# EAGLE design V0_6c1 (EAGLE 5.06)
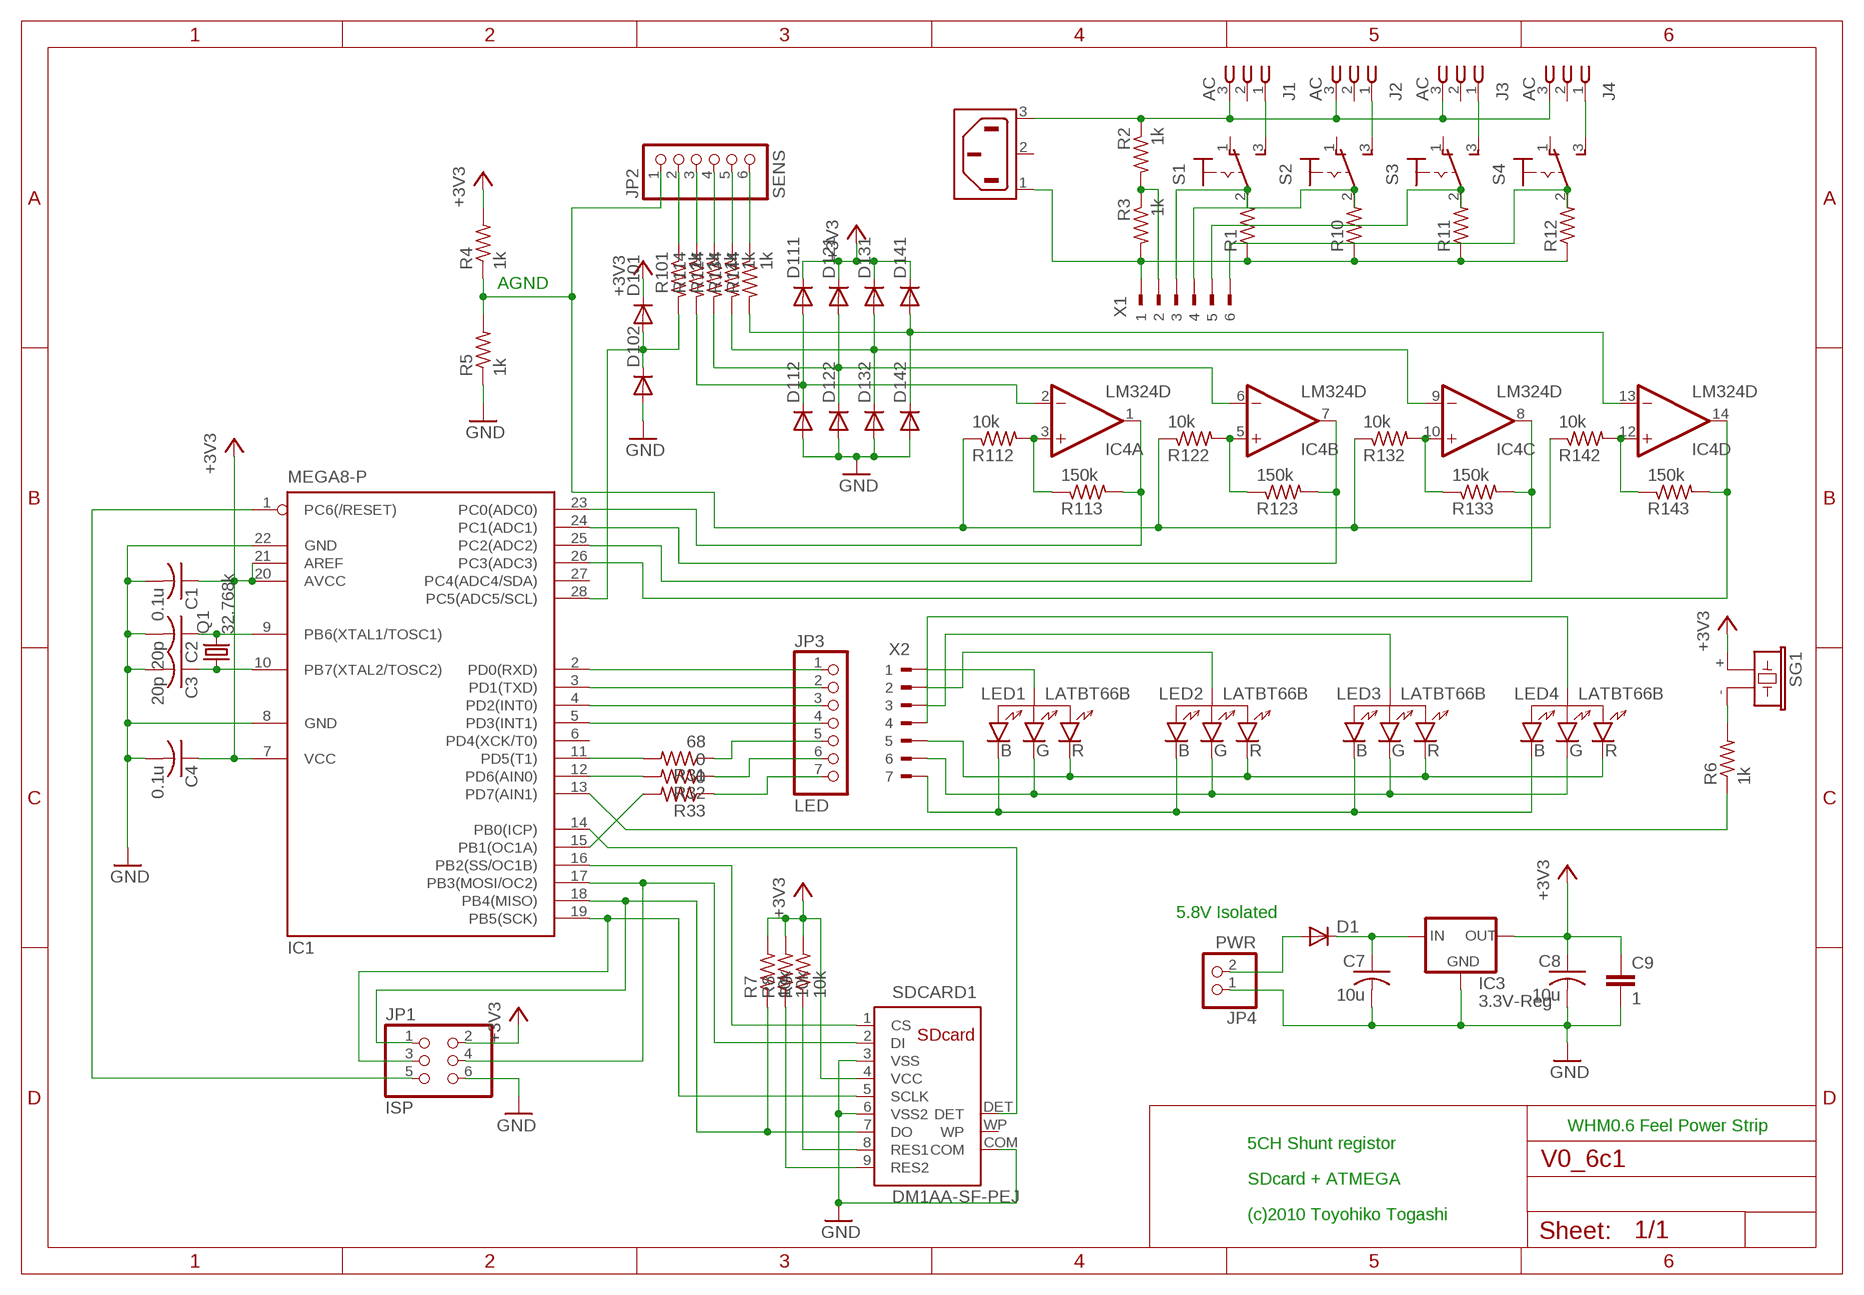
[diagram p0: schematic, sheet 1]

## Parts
C1  0.1u  C-US025-025X050  [C025-025X050]
C2  20p  C-US025-025X050  [C025-025X050]
C3  20p  C-US025-025X050  [C025-025X050]
C4  0.1u  C-US025-025X050  [C025-025X050]
C7  10u  C-US025-040X050  [C025-040X050]
C8  10u  C-US025-040X050  [C025-040X050]
C9  1  C7.5/4  [C7.5B4]
D1  BAS15  [DO34-7]
D101  BAS15  [DO34-7]
D102  BAS15  [DO34-7]
D111  BAS15  [DO34-7]
D112  BAS15  [DO34-7]
D121  BAS15  [DO34-7]
D122  BAS15  [DO34-7]
D131  BAS15  [DO34-7]
D132  BAS15  [DO34-7]
D141  BAS15  [DO34-7]
D142  BAS15  [DO34-7]
IC1  MEGA8-P  [DIL28-3]
IC3  3.3V-Reg  XC63FPM  [SOT23]
IC4  LM324D  [SO14]
J1  AC  213598-2  [213598-2]
J2  AC  213598-2  [213598-2]
J3  AC  213598-2  [213598-2]
J4  AC  213598-2  [213598-2]
JP1  ISP  PINHD-2X3  [2X03]
JP2  SENS  PINHD-1X6  [1X06]
JP3  LED  PINHD-1X7  [1X07]
JP4  PWR  PINHD-1X2  [1X02]
LED1  LATBT66B  [P-LCC-4]
LED2  LATBT66B  [P-LCC-4]
LED3  LATBT66B  [P-LCC-4]
LED4  LATBT66B  [P-LCC-4]
Q1  32.768k  CRYSTALTC26H  [TC26H]
R1  R-US_R6332  [R6332]
R2  1k  R-US_0204/5  [0204/5]
R3  1k  R-US_0204/5  [0204/5]
R4  1k  R-US_0204/5  [0204/5]
R5  1k  R-US_0204/5  [0204/5]
R6  1k  R-US_0204/5  [0204/5]
R7  10k  R-US_0204/5  [0204/5]
R8  10k  R-US_0204/5  [0204/5]
R9  10k  R-US_0204/5  [0204/5]
R10  R-US_R6332  [R6332]
R11  R-US_R6332  [R6332]
R12  R-US_R6332  [R6332]
R31  68  R-US_0204/5  [0204/5]
R32  0  R-US_0204/5  [0204/5]
R33  0  R-US_0204/5  [0204/5]
R101  1k  R-US_0204/5  [0204/5]
R112  10k  R-US_0204/5  [0204/5]
R113  150k  R-US_0204/5  [0204/5]
R114  1k  R-US_0204/5  [0204/5]
R122  10k  R-US_0204/5  [0204/5]
R123  150k  R-US_0204/5  [0204/5]
R124  1k  R-US_0204/5  [0204/5]
R132  10k  R-US_0204/5  [0204/5]
R133  150k  R-US_0204/5  [0204/5]
R134  1k  R-US_0204/5  [0204/5]
R142  10k  R-US_0204/5  [0204/5]
R143  150k  R-US_0204/5  [0204/5]
R144  1k  R-US_0204/5  [0204/5]
S1  320-916  [320-916]
S2  320-916  [320-916]
S3  320-916  [320-916]
S4  320-916  [320-916]
SDCARD1  DM1AA-SF-PEJ  [DM1AA]
SG1  F/CM12P  [F/CM12P]
X1  90-6  [90-6]
X2  90-7  [90-7]
X3  6ESRM-P  [6ESRM-P]

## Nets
+3V3: C1.1 C4.1 C8.1 C9.1 D101.C D111.C D121.C D131.C D141.C IC1.7(VCC) IC1.20(AVCC) IC1.21(AREF) IC3.2(OUT) JP1.2 R4.2 R7.2 R8.2 R9.2 SDCARD1.4(VCC) SG1.+
GND: C1.2 C2.2 C3.2 C4.2 C7.2 C8.2 C9.2 D102.A D112.A D122.A D132.A D142.A IC1.8(GND) IC1.22(GND) IC3.1(GND) JP1.6 JP4.1 R5.1 SDCARD1.3(VSS) SDCARD1.6(VSS2) SDCARD1.COM
N$2: D101.A D102.C IC1.28(PC5(ADC5/SCL)) R101.2
N$3: LED1.P$1 LED2.P$1 LED3.P$1 LED4.P$1 X2.5
N$4: D121.A D122.C IC4.6(B:-IN) R124.2
N$5: IC1.24(PC1(ADC1)) IC4.7(B:OUT) R123.2
N$6: D1.A JP4.2
N$7: C2.1 IC1.9(PB6(XTAL1/TOSC1)) Q1.2
N$8: LED1.P$4 LED2.P$4 LED3.P$4 LED4.P$4 X2.6
N$9: IC1.1(PC6(/RESET)) JP1.5
N$10: IC1.11(PD5(T1)) R31.2
N$11: C3.1 IC1.10(PB7(XTAL2/TOSC2)) Q1.1
N$12: JP2.2 R101.1
N$13: JP2.3 R114.1
N$14: IC1.3(PD1(TXD)) JP3.2
N$15: JP2.4 R124.1
N$16: IC1.4(PD2(INT0)) JP3.3
N$17: IC1.19(PB5(SCK)) JP1.3 SDCARD1.5(SCLK)
N$18: IC1.5(PD3(INT1)) JP3.4
N$19: IC4.3(A:+IN) R112.2 R113.1
N$20: IC4.5(B:+IN) R122.2 R123.1
N$21: IC1.13(PD7(AIN1)) R6.1
N$22: JP2.5 R134.1
N$23: IC1.23(PC0(ADC0)) IC4.1(A:OUT) R113.2
N$24: JP2.6 R144.1
N$25: IC1.2(PD0(RXD)) JP3.1
N$26: R6.2 SG1.-
N$27: JP3.5 R31.1
N$28: JP3.6 R32.1
N$29: IC4.10(C:+IN) R132.2 R133.1
N$30: JP3.7 R33.1
N$31: D111.A D112.C IC4.2(A:-IN) R114.2
N$32: IC1.17(PB3(MOSI/OC2)) JP1.4 SDCARD1.2(DI)
N$33: IC1.18(PB4(MISO)) JP1.1 R7.1 SDCARD1.7(DO)
N$34: JP2.1 R4.1 R5.2 R112.1 R122.1 R132.1 R142.1
N$35: IC1.15(PB1(OC1A)) R33.2
N$36: LED1.P$3 LED2.P$3 LED3.P$3 LED4.P$3 X2.7
N$37: LED1.P$2 X2.1
N$38: IC4.12(D:+IN) R142.2 R143.1
N$39: IC1.16(PB2(SS/OC1B)) SDCARD1.1(CS)
N$40: D131.A D132.C IC4.9(C:-IN) R134.2
N$41: R8.1 SDCARD1.9(RES2)
N$42: R9.1 SDCARD1.8(RES1)
N$43: IC1.14(PB0(ICP)) SDCARD1.DET
N$44: LED2.P$2 X2.2
N$45: LED3.P$2 X2.3
N$46: LED4.P$2 X2.4
N$47: IC1.12(PD6(AIN0)) R32.2
N$48: D141.A D142.C IC4.13(D:-IN) R144.2
N$49: R1.2 S1.2(P) X1.3
N$50: R2.2 R3.1 X1.2
N$51: J1.1 S1.3(S)
N$52: IC1.25(PC2(ADC2)) IC4.8(C:OUT) R133.2
N$53: IC1.26(PC3(ADC3)) IC4.14(D:OUT) R143.2
N$54: J1.3 J2.3 J3.3 J4.3 R2.1 X3.3(AC2)
N$55: R1.1 R3.2 R10.1 R11.1 R12.1 X1.1 X3.1(AC1)
N$56: C7.1 D1.C IC3.3(IN)
N$57: R10.2 S2.2(P) X1.4
N$58: R11.2 S3.2(P) X1.5
N$59: R12.2 S4.2(P) X1.6
N$60: J2.1 S2.3(S)
N$61: J3.1 S3.3(S)
N$62: J4.1 S4.3(S)
Unconnected: IC1.6(PD4(XCK/T0)) IC1.27(PC4(ADC4/SDA)) J1.2 J2.2 J3.2 J4.2 S1.1(O) S2.1(O) S3.1(O) S4.1(O) SDCARD1.WP X3.2(SH)

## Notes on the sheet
- AGND
- 5.8V Isolated
- WHM0.6 Feel Power Strip
- 5CH Shunt registor
- SDcard + ATMEGA
- (c)2010 Toyohiko Togashi

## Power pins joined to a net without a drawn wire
V+: IC4.4(P:V+)
V-: IC4.11(P:V-)

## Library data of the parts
C1-C4 C7 C8 = rcl:C-US: CAPACITOR, American symbol
C9 = capacitor-wima:C: CAPACITOR
D1 D101 D102 D111 D112 D121 D122 D131 D132 D141 D142 = diode:BAS15: DIODE
IC1 = atmel:MEGA8-P: MICROCONTROLLER 8 Kbytes FLASH, 1 kbytes SRAM, 512 bytes EEPROM, USART, 4-channel 10 bit ADC, 2-channel 8 bit ADC Pin compatible with Atmega48, ATMega88, ATMega168 Source: avr.lbr
IC3 = v-reg:XC63FP: Positiv Voltage Regulators www.torex.co.jp/english/product/pro02/pdf/0201_xc62fp.pdf
IC4 = linear:LM324: OP AMP
J1-J4 = con-amp:213598-2: AC Jack Source: ENG_CD_213598_M.pdf
JP1 = pinhead:PINHD-2X3: PIN HEADER
JP2 = pinhead:PINHD-1X6: PIN HEADER
JP3 = pinhead:PINHD-1X7: PIN HEADER
JP4 = pinhead:PINHD-1X2: PIN HEADER
LED1-LED4 = TOG:LATBT66B: RGB LED SMD
Q1 = crystal:CRYSTAL: CRYSTAL
R1-R12 R31-R33 R101 R112-R114 R122-R124 R132-R134 R142-R144 = rcl:R-US_: RESISTOR, American symbol
S1-S4 = switch:320-916: TOGGLE SWITCH distributor RS Components
SDCARD1 = TOG:DM1AA-SF-PEJ: SDcard connector HIROSE
SG1 = buzzer:F/CM12P: BUZZER
X1 = con-weidmueller-sl35:90-6: WEIDMUELLER CLAMP CONNECTOR
X2 = con-weidmueller-sl35:90-7: WEIDMUELLER CLAMP CONNECTOR
X3 = con-tycoelectronics:6ESRM-P: AC Connector 120/250 VAC Source: http://catalog.tycoelectronics.com .. ENG_DS_1654001_1099_SR_0406.pdf

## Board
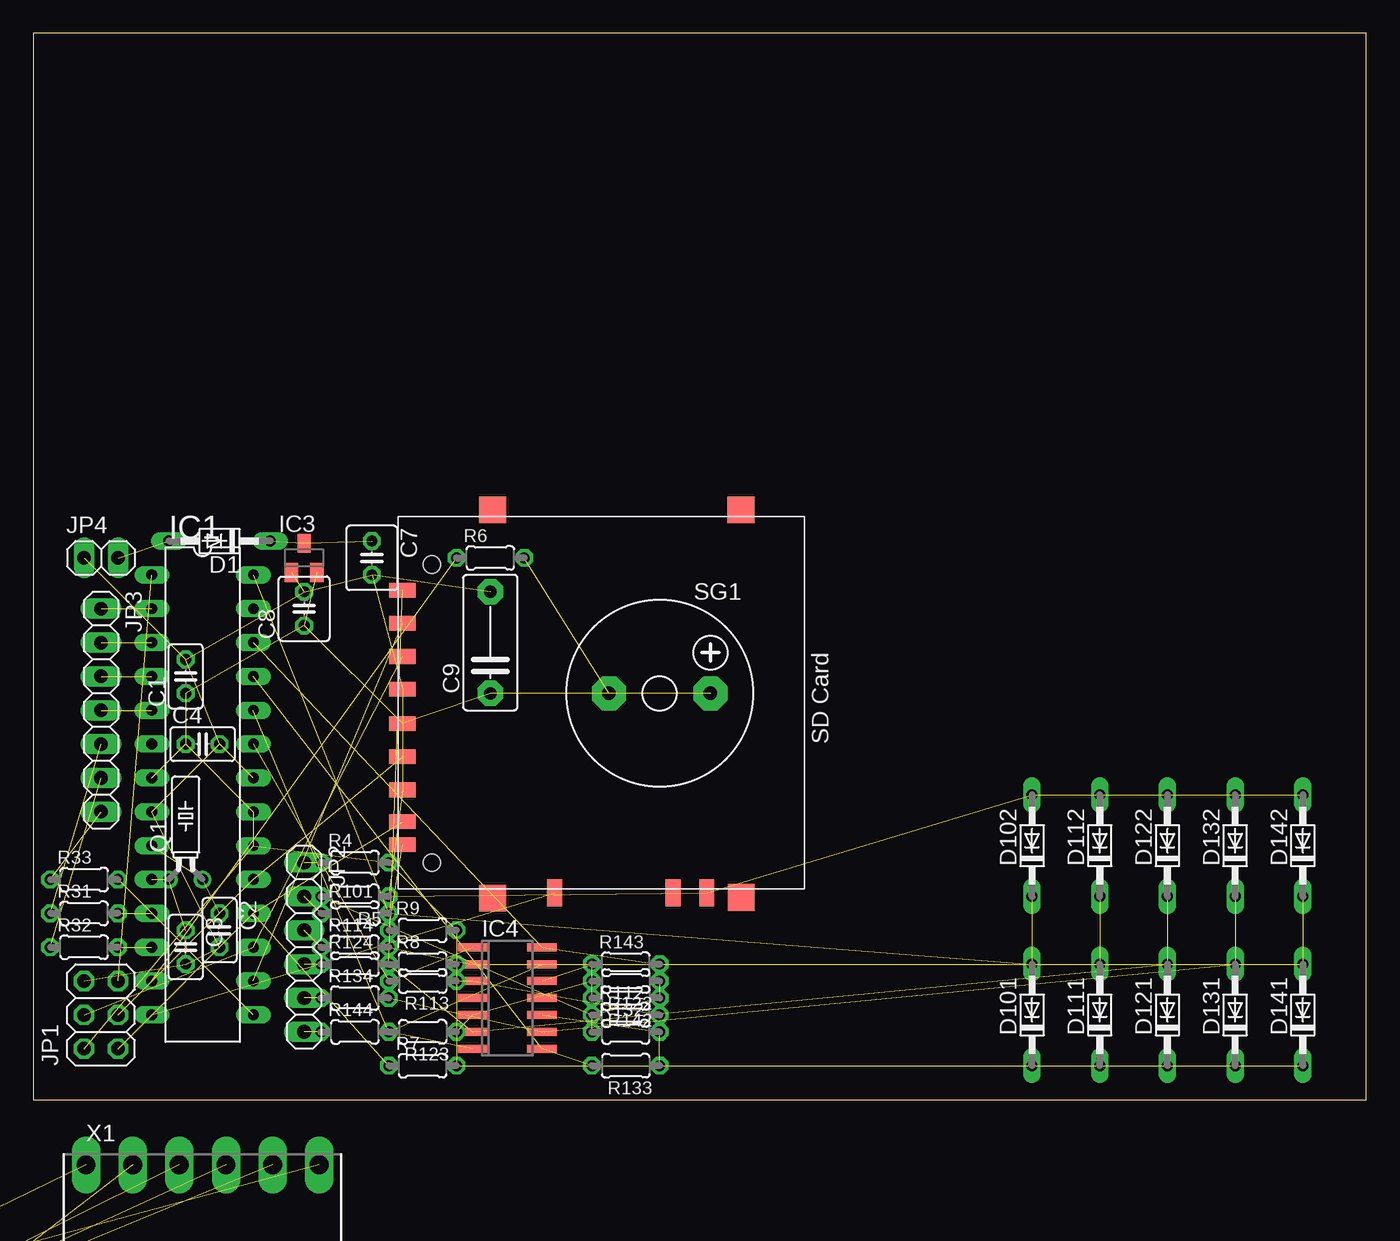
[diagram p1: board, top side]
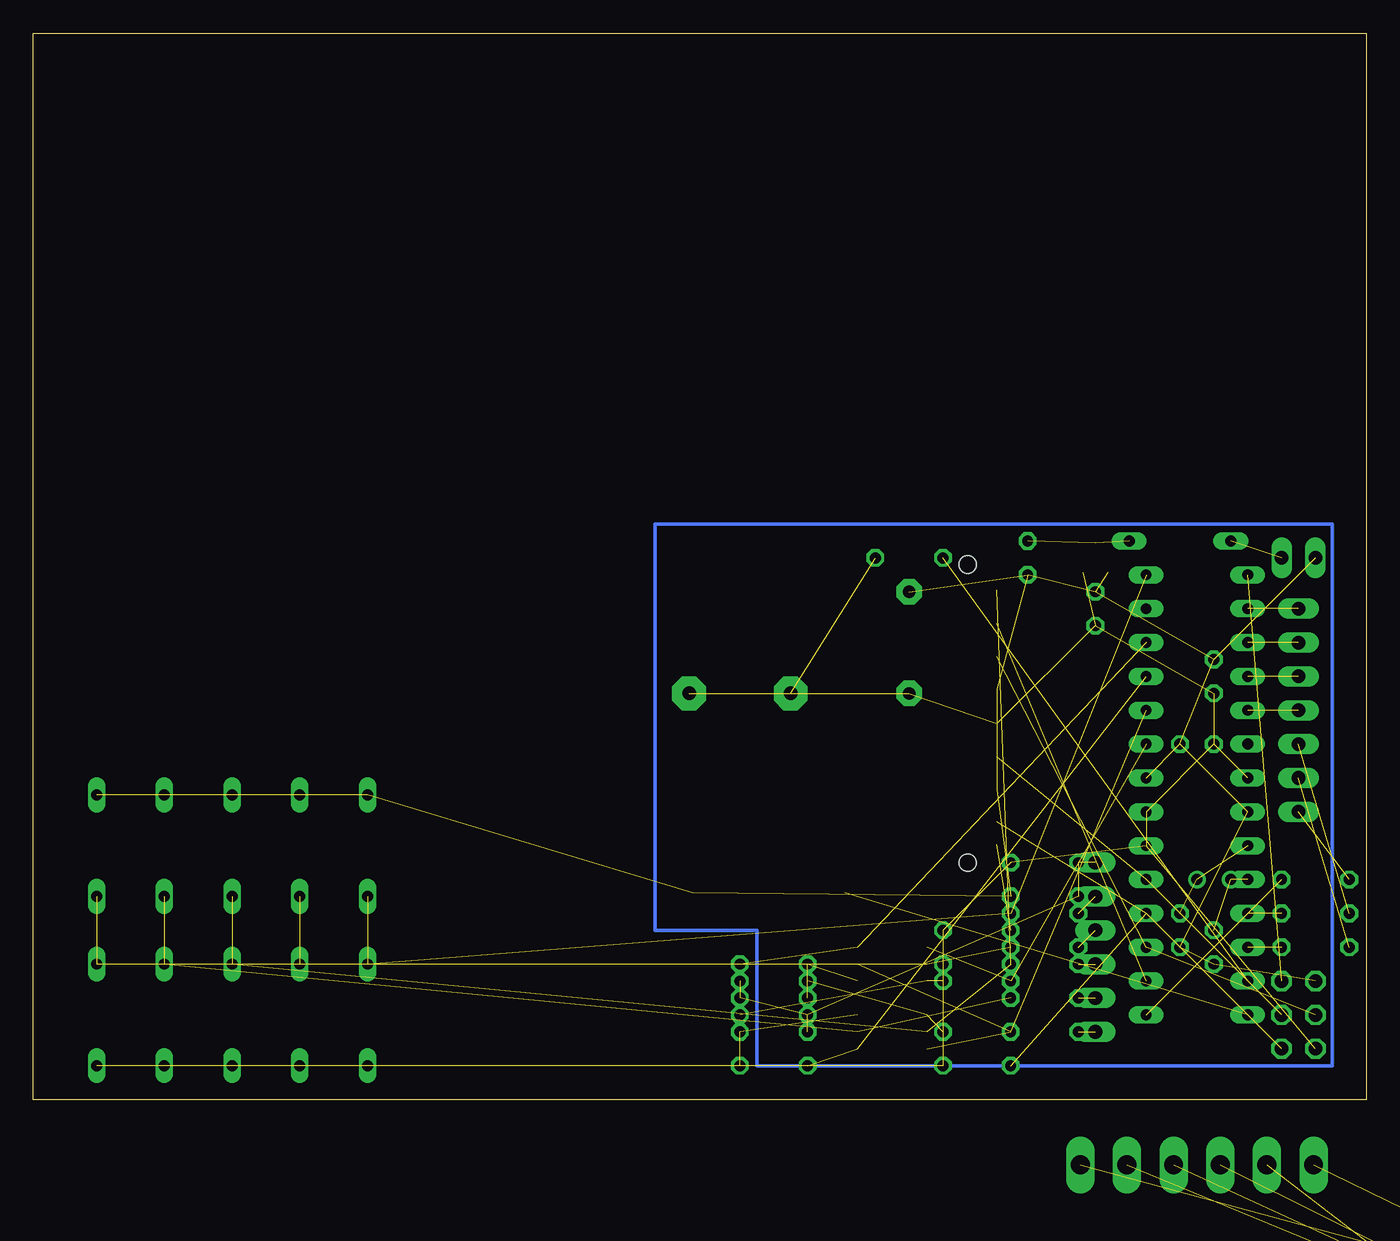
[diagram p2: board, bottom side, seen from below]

Size 100 x 80 mm. Coordinates in mm from the lower left corner, seen from the top.
Outline: 0,0 100,0 100,80 0,80 0,0
Copper layers (1*16): Top 0.035mm / dielectric 1.5mm / Bottom 0.035mm
Design rules "default": minimum track width 10mil, minimum drill 24mil, track to track 8mil, track to pad 8mil, pad to pad 8mil, via to via 8mil, smd to smd 8mil, copper to edge 40mil, drill to drill 8mil, minimum pad ring 10mil, minimum via ring 8mil, stop-mask expansion 4mil, vias tented up to drill 0mil, thermal gap 10mil

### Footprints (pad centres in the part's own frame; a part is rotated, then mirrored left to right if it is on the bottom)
C025-025X050 = drill 0.813 octagon: 1 -1.27,0; 2 1.27,0
C025-040X050 = drill 0.813 octagon: 1 -1.27,0; 2 1.27,0
C7.5B4 = drill 0.914 pad 1.905 octagon: 1 -3.81,0; 2 3.81,0
DO34-7 = drill 0.813 long: A 3.81,0; C -3.81,0
DIL28-3 = drill 0.813 long: 1 -16.51,-3.81; 2 -13.97,-3.81; 3 -11.43,-3.81; 4 -8.89,-3.81; 5 -6.35,-3.81; 6 -3.81,-3.81; 7 -1.27,-3.81; 8 1.27,-3.81; 9 3.81,-3.81; 10 6.35,-3.81; 11 8.89,-3.81; 12 11.43,-3.81; 13 13.97,-3.81; 14 16.51,-3.81; 15 16.51,3.81; 16 13.97,3.81; 17 11.43,3.81; 18 8.89,3.81; 19 6.35,3.81; 20 3.81,3.81; 21 1.27,3.81; 22 -1.27,3.81; 23 -3.81,3.81; 24 -6.35,3.81; 25 -8.89,3.81; 26 -11.43,3.81; 27 -13.97,3.81; 28 -16.51,3.81
SOT23 = smd 1 x 1.4: 1 -0.95,-1.1; 2 0.95,-1.1; 3 0,1.1
SO14 = smd 0.6 x 2.2: 1 -3.81,-2.6; 2 -2.54,-2.6; 3 -1.27,-2.6; 4 0,-2.6; 5 1.27,-2.6; 6 2.54,-2.6; 7 3.81,-2.6; 8 3.81,2.6; 9 2.54,2.6; 10 1.27,2.6; 11 0,2.6; 12 -1.27,2.6; 13 -2.54,2.6; 14 -3.81,2.6
213598-2 = drill 2.6 pad 3.6 round: 1 -6.35,0; 2 6.35,0; 3 0,-3.38
2X03 = drill 1.016 octagon: 1 -2.54,-1.27; 2 -2.54,1.27; 3 0,-1.27; 4 0,1.27; 5 2.54,-1.27; 6 2.54,1.27
1X06 = drill 1.016 long: 1 -6.35,0; 2 -3.81,0; 3 -1.27,0; 4 1.27,0; 5 3.81,0; 6 6.35,0
1X07 = drill 1.016 long: 1 -7.62,0; 2 -5.08,0; 3 -2.54,0; 4 0,0; 5 2.54,0; 6 5.08,0; 7 7.62,0
1X02 = drill 1.016 long: 1 -1.27,0; 2 1.27,0
P-LCC-4 = smd 0.813 x 1.676: P$1 -0.8,-1.5; P$2 -0.8,1.5; P$3 0.8,1.5; P$4 0.8,-1.5
TC26H = drill 0.813 round: 1 -1.27,0; 2 1.27,0
R6332 = smd 1 x 3.2: 1 -3.1,0; 2 3.1,0
0204/5 = drill 0.813 octagon: 1 -2.54,0; 2 2.54,0
320-916 = drill 2.007 long: 1 0,4.013; 2 0,0; 3 0,-4.013
DM1AA = smd 1.1 x 2: 1 3.98,14.22; 2 1.49,14.22; 3 -0.95,14.22; 4 -3.54,14.22; 5 -6.03,14.22; 6 -8.52,14.22; 7 -10.91,14.22; 8 -12.615,14.22; 9 6.47,14.22 | smd 2 x 1.1: COM -16.24,-8.62; DET -16.24,2.81; WP -16.24,-6.08 | smd 2.007 x 2.007: FG -16.64,7.455; P$13 12.5,7.455; P$14 12.5,-11.19; P$15 -16.59,-11.21 | hole 1.3: 8.39,12; -13.97,12
F/CM12P = drill 1.016 pad 2.54 octagon: + 3.81,0; - -3.81,0
90-6 = drill 1.422 long: 1 -8.75,5.25; 2 -5.25,5.25; 3 -1.75,5.25; 4 1.75,5.25; 5 5.25,5.25; 6 8.75,5.25
90-7 = drill 1.422 long: 1 -10.5,5.25; 2 -7,5.25; 3 -3.5,5.25; 4 0,5.25; 5 3.5,5.25; 6 7,5.25; 7 10.5,5.25
6ESRM-P = drill 1.6 pad 2.6 round: 1 -9.1,9.7; 2 0,9.7; 3 9.1,9.7 | hole 3.6: -20,0; 20,0

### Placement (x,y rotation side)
C1  11.43,31.75 90 top
C2  13.97,12.7 270 top
C3  11.43,11.43 270 top
C4  12.7,26.67 0 top
C7  25.4,40.64 270 top
C8  20.32,36.83 90 top
C9  34.29,34.29 90 top
D1  13.97,41.91 180 top
D101  74.93,6.35 90 top
D102  74.93,19.05 90 top
D111  80.01,6.35 90 top
D112  80.01,19.05 90 top
D121  85.09,6.35 90 top
D122  85.09,19.05 90 top
D131  90.17,6.35 90 top
D132  90.17,19.05 90 top
D141  95.25,6.35 90 top
D142  95.25,19.05 90 top
IC1  12.7,22.86 270 top
IC3  20.32,40.64 0 top
IC4  35.56,7.62 270 top
J1  not placed on the board
J2  not placed on the board
J3  not placed on the board
J4  not placed on the board
JP1  5.08,6.35 90 top
JP2  20.32,11.43 270 top
JP3  5.08,29.21 270 top
JP4  5.08,40.64 0 top
LED1  not placed on the board
LED2  not placed on the board
LED3  not placed on the board
LED4  not placed on the board
Q1  11.43,16.51 0 top
R1  not placed on the board
R2  not placed on the board
R3  not placed on the board
R4  24.13,17.78 0 top
R5  24.13,15.24 180 top
R6  34.29,40.64 0 top
R7  29.21,2.54 0 top
R8  29.21,10.16 0 top
R9  29.21,12.7 0 top
R10  not placed on the board
R11  not placed on the board
R12  not placed on the board
R31  3.81,13.97 0 top
R32  3.81,11.43 0 top
R33  3.81,16.51 0 top
R101  24.13,13.97 0 top
R112  44.45,6.35 0 top
R113  29.21,8.89 180 top
R114  24.13,11.43 0 top
R122  44.45,8.89 180 top
R123  29.21,5.08 180 top
R124  24.13,10.16 0 top
R132  44.45,5.08 0 top
R133  44.45,2.54 180 top
R134  24.13,7.62 0 top
R142  44.45,7.62 180 top
R143  44.45,10.16 0 top
R144  24.13,5.08 0 top
S1  not placed on the board
S2  not placed on the board
S3  not placed on the board
S4  not placed on the board
SDCARD1  41.91,31.75 90 top
SG1  46.99,30.48 0 top
X1  not placed on the board
X2  not placed on the board
X3  not placed on the board

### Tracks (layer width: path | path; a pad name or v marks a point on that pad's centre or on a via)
+3V3  (19 unrouted)
GND  (20 unrouted)
N$1
  Bottom 0.254: 2.54,2.54 2.54,43.18 53.34,43.18 53.34,12.7 45.72,12.7 45.72,2.54 2.54,2.54
N$2  (3 unrouted)
N$3  (4 unrouted)
N$4  (3 unrouted)
N$5  (2 unrouted)
N$6  (1 unrouted)
N$7  (2 unrouted)
N$8  (4 unrouted)
N$9  (1 unrouted)
N$10  (1 unrouted)
N$11  (2 unrouted)
N$12  (1 unrouted)
N$13  (1 unrouted)
N$14  (1 unrouted)
N$15  (1 unrouted)
N$16  (1 unrouted)
N$17  (2 unrouted)
N$18  (1 unrouted)
N$19  (2 unrouted)
N$20  (2 unrouted)
N$21  (1 unrouted)
N$22  (1 unrouted)
N$23  (2 unrouted)
N$24  (1 unrouted)
N$25  (1 unrouted)
N$26  (1 unrouted)
N$27  (1 unrouted)
N$28  (1 unrouted)
N$29  (2 unrouted)
N$30  (1 unrouted)
N$31  (3 unrouted)
N$32  (2 unrouted)
N$33  (3 unrouted)
N$34  (6 unrouted)
N$35  (1 unrouted)
N$36  (4 unrouted)
N$37  (1 unrouted)
N$38  (2 unrouted)
N$39  (1 unrouted)
N$40  (3 unrouted)
N$41  (1 unrouted)
N$42  (1 unrouted)
N$43  (1 unrouted)
N$44  (1 unrouted)
N$45  (1 unrouted)
N$46  (1 unrouted)
N$47  (1 unrouted)
N$48  (3 unrouted)
N$49  (2 unrouted)
N$50  (2 unrouted)
N$51  (1 unrouted)
N$52  (2 unrouted)
N$53  (2 unrouted)
N$54  (5 unrouted)
N$55  (6 unrouted)
N$56  (2 unrouted)
N$57  (2 unrouted)
N$58  (2 unrouted)
N$59  (2 unrouted)
N$60  (1 unrouted)
N$61  (1 unrouted)
N$62  (1 unrouted)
